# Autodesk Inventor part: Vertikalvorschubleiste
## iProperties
Created: 2012-09
Part Number: Vertikalvorschubleiste
Document SubType Name: Modeling
Designer: Jonathan
Density: 1 g/cm^3
Author: Jonathan
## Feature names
1. Extrusion1
2. Extrusion2
3. Extrusion3
4. Extrusion4
5. Bohrung1 [Hole]
6. Bohrung2 [Hole]
7. Extrusion5
8. Bohrung3 [Hole]
9. Extrusion6
10. Bohrung4 [Hole]
11. Extrusion7
12. Fase1 [Chamfer]
